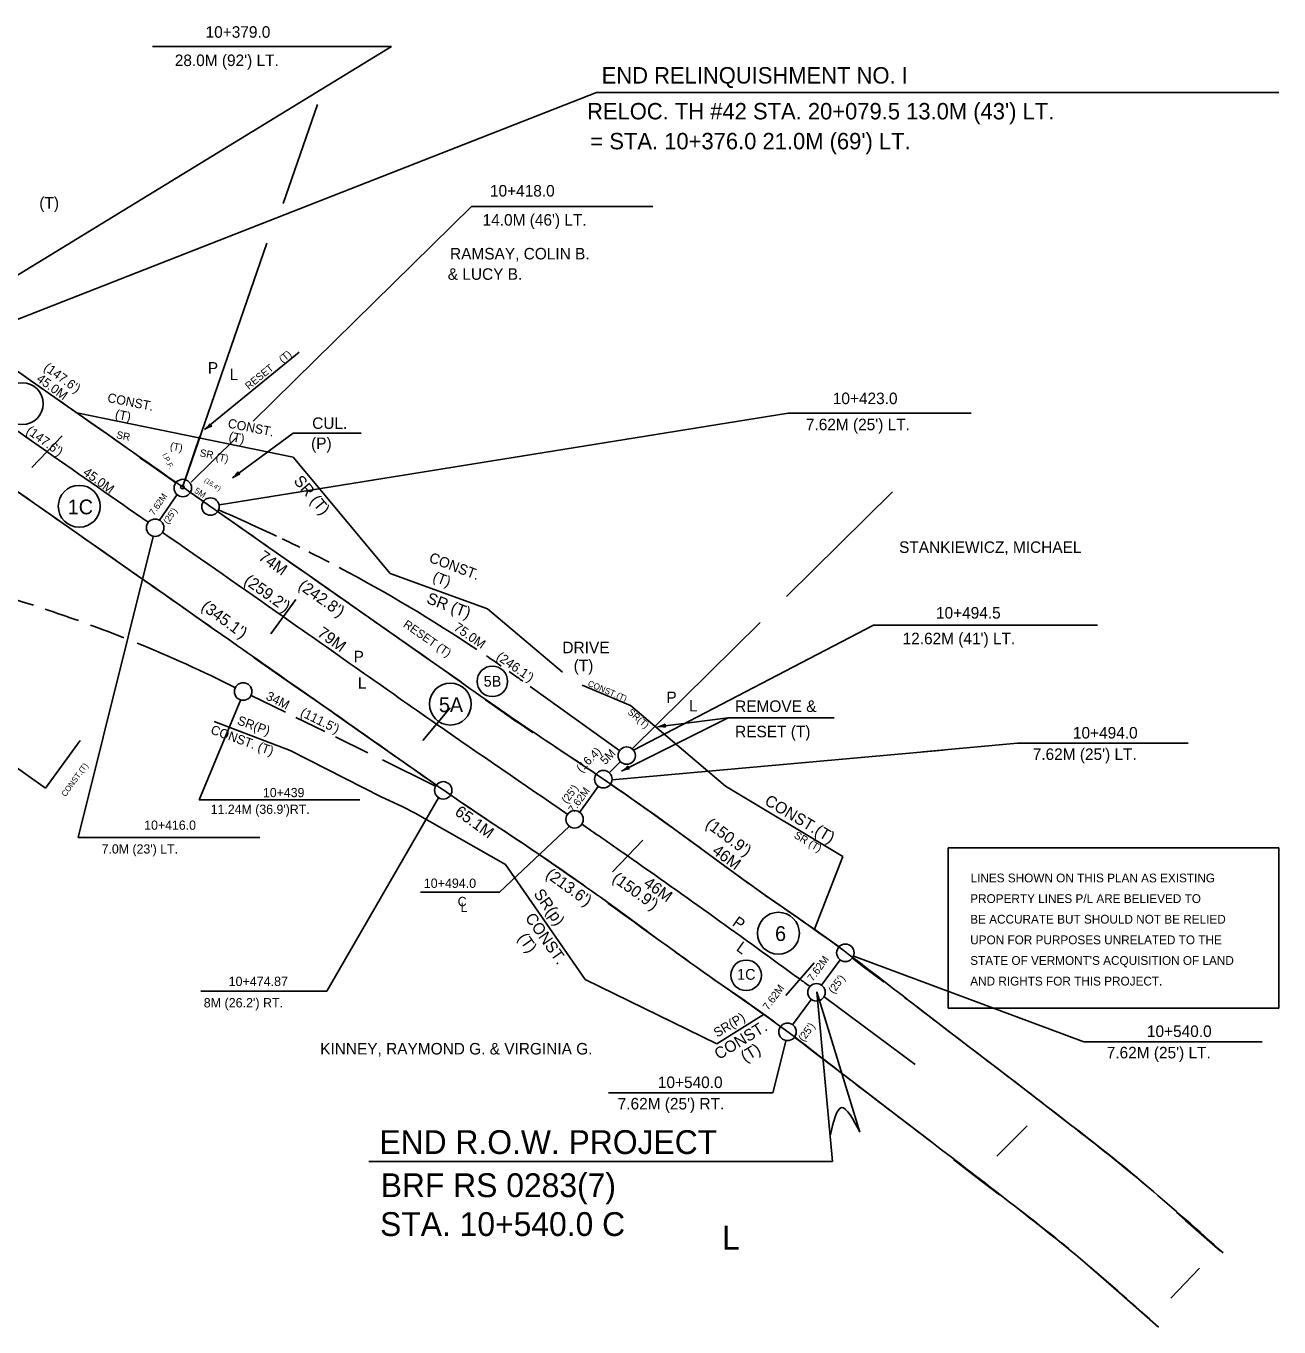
# Model space of a CAD drawing. Extents: x 624 to 1448, y 1599 to 1865.
# Drawn here: x 1254.2 to 1448.1, y 1600.9 to 1802.2 of the extents above; entities that cross this region are included whole.
import ezdxf

# ---------------------------------------------------------------- set-up
doc = ezdxf.new("R2010")
doc.units = 0
for name, color, linetype in [('C_I', 7, 'Continuous'), ('C_TIC', 7, 'Continuous'), ('CPSM', 7, 'Continuous'), ('L_A', 7, 'Continuous'), ('L_C', 7, 'Continuous'), ('L_I', 7, 'Continuous'), ('Level 16', 7, 'Continuous'), ('Level 30', 7, 'Continuous'), ('Level 60', 7, 'Continuous'), ('ODIML_P', 7, 'Continuous')]:
    doc.layers.add(name, color=color, linetype=linetype)

msp = doc.modelspace()

# ---------------------------------------------------------------- linework, layer by layer
at = {"layer": 'C_I'}
for p, q in [((1281.82, 1739.73), (1296.45, 1751.7)), ((1281.06, 1738.74), (1278.38, 1730.83)), ((1286.15, 1732.27), (1295.51, 1739.2)), ((1295.51, 1739.2), (1306.06, 1739.2)), ((1346.34, 1686.92), (1362.84, 1695.16)), ((1351.88, 1693.76), (1362.84, 1695.16)), ((1362.84, 1695.16), (1379.23, 1695.16)), ((1247.89, 1690.87), (1257.19, 1684.28)), ((1262.56, 1691.67), (1257.19, 1684.28))]:
    msp.add_line(p, q, dxfattribs=at)
msp.add_circle((1278.4, 1730.84), 0.285, dxfattribs=at)
at = {"layer": 'C_TIC'}
for p, q in [((1330.91, 1700.92), (1331.07, 1700.8)), ((1289.03, 1698.61), (1294.33, 1696.01)), ((1332.19, 1700.01), (1346.07, 1690.07)), ((1295.93, 1695.22), (1300.42, 1693.02)), ((1302.09, 1692.2), (1307.1, 1689.74)), ((1309.36, 1688.63), (1317.57, 1684.59)), ((1396.85, 1675.03), (1448.02, 1675.03)), ((1396.85, 1675.03), (1396.86, 1650.25)), ((1448.02, 1675.03), (1448.02, 1650.25)), ((1396.86, 1650.25), (1448.02, 1650.25))]:
    msp.add_line(p, q, dxfattribs=at)
for radius, start, end in [(247.62, 64.6157, 66.9012), (247.62, 63.6919, 64.3964), (247.62, 62.5203, 63.3373), (223.76, 72.1716, 79.6486), (247.62, 56.3674, 62.1142), (223.76, 70.2871, 71.6839), (223.76, 68.3594, 69.7794), (223.76, 63.542, 67.7975), (247.62, 55.3158, 55.9578), (247.62, 54.4164, 54.9691)]:
    msp.add_arc((1186.82, 1499.54), radius, start, end, dxfattribs=at)
at = {"layer": 'CPSM'}
for p, q in [((1342.48, 1791.88), (1237.06, 1750.6)), ((1342.48, 1791.88), (1448.06, 1791.88)), ((1378.99, 1626.54), (1376.57, 1652.79)), ((1376.57, 1652.79), (1383.23, 1631.07)), ((1307.26, 1626.54), (1378.99, 1626.54))]:
    msp.add_line(p, q, dxfattribs=at)
msp.add_spline([(1383.23, 1631.07), (1380.36, 1634.86), (1378.62, 1630.52)], degree=3, dxfattribs=at)
at = {"layer": 'L_C'}
for p in [(1242.65, 1757.37), (1273.78, 1798.99)]:
    msp.add_line(p, (1310.72, 1798.99), dxfattribs=at)
for centre, radius in [((1253.6, 1743.74), 3.24), ((1262.42, 1727.87), 3.24), ((1326.35, 1700.79), 2.36), ((1319.85, 1697.28), 3.24), ((1370.61, 1661.83), 3.24), ((1365.61, 1655.33), 2.36)]:
    msp.add_circle(centre, radius, dxfattribs=at)
at = {"layer": 'L_I'}
for p, q in [((1293.98, 1774.7), (1299.27, 1790.02)), ((1298.93, 1750.47), (1323.11, 1774.25)), ((1323.11, 1774.25), (1351.17, 1774.25)), ((1278.83, 1731.95), (1291.47, 1768.56)), ((1289.34, 1741.04), (1298.93, 1750.47)), ((1284.11, 1728.09), (1372.1, 1742.25)), ((1372.1, 1742.25), (1400.44, 1742.25)), ((1279.74, 1731.61), (1286.71, 1738.45)), ((1274.82, 1725.72), (1277.58, 1729.67)), ((1388.28, 1730.13), (1371.86, 1713.93)), ((1273.85, 1723.21), (1262.26, 1676.66)), ((1367.78, 1709.91), (1347.98, 1690.37)), ((1348.18, 1690.14), (1385.32, 1709.5)), ((1385.32, 1709.5), (1419.96, 1709.5)), ((1287.44, 1697.97), (1280.98, 1682.48)), ((1392.95, 1689.89), (1407.6, 1691.21)), ((1407.6, 1691.21), (1434, 1691.21)), ((1346.15, 1688.38), (1344.43, 1686.67)), ((1344.87, 1685.58), (1396.03, 1690.17)), ((1280.98, 1682.48), (1305.84, 1682.48)), ((1318.01, 1682.79), (1300.75, 1652.89)), ((1338.26, 1678.37), (1327.43, 1668.2)), ((1262.26, 1676.66), (1290.38, 1676.66)), ((1315.24, 1668.2), (1327.43, 1668.2)), ((1382.26, 1658.31), (1417.89, 1645.05)), ((1377.3, 1653.8), (1380.18, 1657.73)), ((1281.23, 1652.89), (1300.75, 1652.89)), ((1377.67, 1652.01), (1391.78, 1641.51)), ((1372.81, 1647.65), (1375.71, 1651.62)), ((1369.77, 1637.15), (1371.74, 1645.14)), ((1417.89, 1645.05), (1445.45, 1645.05)), ((1344.31, 1637.15), (1369.77, 1637.15))]:
    msp.add_line(p, q, dxfattribs=at)
msp.add_lwpolyline([(1342.73, 1684.55), (1339.85, 1680.52)], dxfattribs=at)
for centre in [(1278.45, 1730.69), (1282.73, 1727.83), (1274.17, 1724.55), (1287.79, 1699.22), (1347.14, 1689.31), (1343.52, 1685.66), (1318.75, 1683.93), (1339.07, 1679.45), (1380.97, 1658.81), (1376.5, 1652.7), (1372.02, 1646.58)]:
    msp.add_circle(centre, 1.35, dxfattribs=at)
for points in [[(1238.24, 1749.77), (1257.42, 1736.33), (1273.09, 1725.39)], [(1275.33, 1723.83), (1294, 1710.8), (1317.71, 1694.18), (1337.94, 1680.26)], [(1340.29, 1678.64), (1347.28, 1673.79), (1373.95, 1654.72), (1375.49, 1653.6)]]:
    msp.add_spline(points, degree=3, dxfattribs=at)
at = {"layer": 'Level 16'}
for p, q in [((1282.67, 1740.64), (1282.73, 1740.4)), ((1282.64, 1740.5), (1282.53, 1740.32)), ((1282.8, 1740.29), (1282.59, 1740.24)), ((1282.94, 1740.28), (1282.73, 1740.4)), ((1286.98, 1733.04), (1286.87, 1732.86)), ((1287.13, 1732.83), (1286.93, 1732.78)), ((1287.01, 1733.18), (1287.07, 1732.94)), ((1287.28, 1732.82), (1287.07, 1732.94)), ((1352.97, 1694.06), (1352.79, 1693.95)), ((1353.01, 1693.8), (1352.8, 1693.85)), ((1353.07, 1694.17), (1353.01, 1693.93)), ((1353.14, 1693.72), (1353.01, 1693.93)), ((1347.28, 1687.54), (1347.14, 1687.38)), ((1347.4, 1687.31), (1347.19, 1687.29)), ((1347.34, 1687.68), (1347.36, 1687.43)), ((1347.54, 1687.27), (1347.36, 1687.43))]:
    msp.add_line(p, q, dxfattribs=at)
for centre, start, end in [((1279.78, 1742.47), 306.5421, 327.7653), ((1283.85, 1736.98), 105.345, 126.5683), ((1284.12, 1735.01), 306.5421, 327.7653), ((1288.19, 1729.52), 105.345, 126.5683), ((1351.37, 1697.15), 278.5256, 299.7488), ((1352.39, 1690.38), 77.3285, 98.5518), ((1344.81, 1689.98), 296.5256, 317.7488), ((1347.87, 1683.86), 95.3285, 116.5518)]:
    msp.add_arc(centre, 3.42, start, end, dxfattribs=at)
at = {"layer": 'Level 30'}
for p, q in [((1347.71, 1697.05), (1340.22, 1700.19)), ((1309.13, 1682.95), (1312.39, 1681.44))]:
    msp.add_line(p, q, dxfattribs=at)
for points in [[(1295.53, 1735.49), (1262.05, 1742.32)], [(1310.56, 1717.5), (1295.53, 1735.49)], [(1325.6, 1711.99), (1310.56, 1717.5)], [(1337.18, 1702.23), (1325.6, 1711.99)], [(1362.44, 1684.59), (1347.71, 1697.05)], [(1295.05, 1690.12), (1283.3, 1694.57)], [(1309.13, 1682.95), (1295.05, 1690.12)], [(1380.56, 1673.7), (1362.44, 1684.59)], [(1328.37, 1672.47), (1314.41, 1680.41), (1312.39, 1681.44)], [(1340.69, 1654.68), (1328.37, 1672.47)], [(1376.18, 1662.45), (1380.56, 1673.7)], [(1361.1, 1644.75), (1340.69, 1654.68)], [(1368.39, 1649.3), (1361.1, 1644.75)]]:
    msp.add_lwpolyline(points, dxfattribs=at)
at = {"layer": 'Level 60'}
for p, q in [((1255.08, 1733.87), (1259.76, 1738.78)), ((1292.06, 1708.15), (1295.93, 1713.45)), ((1315.59, 1691.65), (1319.84, 1696.71)), ((1344.92, 1671.33), (1349.64, 1676.25)), ((1371.76, 1652.18), (1376.15, 1657.26)), ((1404.41, 1627.37), (1409.1, 1632.07)), ((1431.33, 1605.39), (1435.74, 1610.04))]:
    msp.add_line(p, q, dxfattribs=at)
at = {"layer": 'ODIML_P'}
for points in [[(1242.51, 1756), (1248.06, 1752.11), (1254.3, 1747.74), (1260.54, 1743.37), (1266.78, 1739), (1269.31, 1737.23)], [(1245.57, 1735.26), (1251.8, 1730.9), (1258.05, 1726.53), (1264.29, 1722.16), (1270.53, 1717.79), (1271.9, 1716.83), (1273.28, 1715.86), (1278.14, 1712.45), (1283.01, 1709.04), (1285.73, 1707.14)], [(1271.81, 1735.39), (1272.98, 1734.57), (1277.37, 1731.5)], [(1279.62, 1730.02), (1281.66, 1728.59)], [(1283.84, 1727.06), (1286.88, 1724.93), (1291.75, 1721.52), (1297.99, 1717.15), (1304.23, 1712.78), (1310.47, 1708.41), (1316.72, 1704.04), (1321.55, 1700.65)], [(1289.47, 1704.43), (1295.45, 1700.24), (1301.58, 1696.06)], [(1325.29, 1697.94), (1329.12, 1695.26), (1329.9, 1694.71), (1330.64, 1694.21), (1331.33, 1693.74), (1331.98, 1693.3), (1332.68, 1692.83)], [(1301.64, 1696), (1301.74, 1695.93), (1307.98, 1691.56), (1314.27, 1687.16), (1317.7, 1684.76)], [(1336.03, 1690.7), (1338.08, 1689.34), (1339.02, 1688.72), (1339.72, 1688.25), (1340.78, 1687.54), (1341.82, 1686.83), (1342.42, 1686.42)], [(1344.65, 1684.88), (1344.78, 1684.79), (1345.99, 1683.96), (1347.04, 1683.22), (1348.88, 1681.94), (1350.26, 1680.97), (1351.29, 1680.24), (1352.83, 1679.14), (1354.38, 1678.04), (1355.15, 1677.48), (1355.87, 1676.96), (1357.23, 1675.98), (1358.41, 1675.11), (1362.55, 1672.07), (1363.58, 1671.31), (1365.13, 1670.17), (1365.91, 1669.61), (1366.69, 1669.05), (1367.47, 1668.49), (1368.2, 1667.97), (1368.89, 1667.49), (1369.54, 1667.04), (1374.41, 1663.68), (1375.02, 1663.26), (1375.55, 1662.89), (1379.99, 1659.75)], [(1319.91, 1683.21), (1320.55, 1682.76), (1321.34, 1682.21), (1322.07, 1681.71), (1322.76, 1681.24), (1323.41, 1680.8), (1324.64, 1679.98), (1325.71, 1679.27), (1329.47, 1676.78), (1330.41, 1676.16), (1331.11, 1675.69), (1332.16, 1674.98), (1333.21, 1674.27), (1334.76, 1673.2), (1336.11, 1672.27), (1337.29, 1671.45), (1338.33, 1670.73), (1340.13, 1669.47), (1340.48, 1669.23)], [(1344.2, 1666.5), (1345.47, 1665.59), (1346.25, 1665.04), (1346.97, 1664.51), (1348.32, 1663.53), (1349.5, 1662.66), (1351.48, 1661.21)], [(1354.71, 1658.93), (1356.26, 1657.8), (1357.04, 1657.23), (1357.82, 1656.67), (1358.59, 1656.12), (1359.31, 1655.6), (1359.99, 1655.13), (1360.63, 1654.68), (1365.46, 1651.36), (1366.06, 1650.94), (1366.59, 1650.58), (1367.5, 1649.93), (1368.18, 1649.44), (1368.69, 1649.07), (1369.08, 1648.79), (1369.65, 1648.37), (1370.21, 1647.94), (1370.96, 1647.38)], [(1382.07, 1657.97), (1383.38, 1656.97), (1385.39, 1655.44), (1386.95, 1654.25)], [(1390.14, 1651.9), (1391.46, 1650.9), (1397.54, 1646.24), (1403.62, 1641.59), (1406.67, 1639.25), (1411.23, 1635.74), (1415.8, 1632.22), (1417.33, 1631.05), (1418.66, 1630.01), (1419.83, 1629.1), (1420.85, 1628.3), (1421.74, 1627.6), (1422.52, 1626.98), (1423.19, 1626.44), (1423.78, 1625.96), (1424.29, 1625.54), (1424.74, 1625.17), (1425.52, 1624.52), (1426.11, 1624.03), (1426.54, 1623.66), (1427.19, 1623.1), (1427.84, 1622.54), (1428.77, 1621.73)], [(1373.14, 1645.72), (1374.34, 1644.81), (1376.31, 1643.31), (1379.26, 1641.05), (1382.21, 1638.79), (1388.28, 1634.15), (1394.07, 1629.71)], [(1397.69, 1626.84), (1401.83, 1623.66), (1404.82, 1621.36)], [(1408, 1619), (1409.16, 1618.11), (1410.29, 1617.23), (1411.28, 1616.45), (1412.14, 1615.77), (1412.89, 1615.17), (1413.55, 1614.65), (1414.12, 1614.18), (1414.62, 1613.78), (1415.48, 1613.06), (1416.13, 1612.52), (1416.61, 1612.11), (1417.33, 1611.49), (1418.05, 1610.87), (1423.73, 1605.9), (1429.41, 1600.93)], [(1432.19, 1618.63), (1433.59, 1617.41), (1438.96, 1612.71)]]:
    msp.add_lwpolyline(points, dxfattribs=at)
for points in [[(1237.38, 1759.65), (1241.82, 1756.48), (1254.3, 1747.74), (1266.78, 1739), (1279.27, 1730.26), (1282.01, 1728.34), (1291.75, 1721.52), (1304.23, 1712.78), (1316.72, 1704.04), (1329.16, 1695.32), (1341.82, 1686.83), (1354.38, 1678.04), (1366.69, 1669.05), (1379.22, 1660.23), (1391.46, 1650.9), (1403.62, 1641.59), (1415.8, 1632.22), (1427.84, 1622.54), (1439.44, 1612.4)], [(1228.65, 1747.17), (1233, 1744.06), (1245.56, 1735.27), (1258.05, 1726.53), (1270.53, 1717.79), (1273.28, 1715.86), (1283.01, 1709.04), (1295.5, 1700.3), (1307.98, 1691.56), (1320.55, 1682.76), (1333.21, 1674.27), (1345.52, 1665.65), (1357.82, 1656.67), (1370.21, 1647.94), (1382.21, 1638.79), (1394.35, 1629.5), (1406.38, 1620.25), (1418.05, 1610.87), (1429.41, 1600.93)]]:
    msp.add_spline(points, degree=3, dxfattribs=at)

# ---------------------------------------------------------------- texts
at = {"layer": 'C_I'}
for s, p in [('(T)', (1256.25, 1773.91)), ('CUL.', (1298.47, 1739.84)), ('(P)', (1298.3, 1736.72)), ('DRIVE', (1337.19, 1705.14)), ('(T)', (1338.93, 1702.36)), ('REMOVE &', (1363.91, 1696.06)), ('RESET (T)', (1363.91, 1692.14))]:
    msp.add_text(s, height=1.783, dxfattribs=at).set_placement(p)
for s, height, rotation, p in [('(T)', 1.141, 39.2906, (1293.89, 1749.98)), ("(147.6')", 1.426, 324.0348, (1256.81, 1749.06)), ('RESET', 1.141, 39.2906, (1288.67, 1745.85)), ('45.0M', 1.426, 324.0348, (1255.69, 1747.32)), ('CONST.', 1.426, 348.7867, (1266.7, 1744.02)), ('(T)', 1.426, 348.7867, (1267.88, 1741.47)), ('CONST.', 1.426, 348.7867, (1285.33, 1740.06)), ("(147.6')", 1.426, 324.0348, (1254.09, 1739.29)), ('SR', 1.141, 348.7867, (1268.1, 1738.41)), ('(T)', 1.426, 348.7867, (1285.47, 1738.03)), ('(T)', 1.141, 348.7867, (1276.4, 1736.69)), ('SR', 1.141, 348.7867, (1281, 1735.62)), ('I.P.F.', 0.8, 296.5573, (1275.23, 1735.85)), ('(T)', 1.141, 348.7867, (1283.49, 1735.01)), ('45.0M', 1.426, 324.0348, (1262.89, 1732.84)), ('SR (T)', 1.783, 309.9901, (1295.5, 1731.75)), ('5M', 0.948, 327.817, (1280.14, 1730.04)), ("(16.4')", 0.725, 327.817, (1281.69, 1731.7)), ('7.62M', 1, 55.1081, (1273.98, 1726.39)), ("(25')", 1, 55.1081, (1276.15, 1725.03)), ('74M', 1.783, 324.9475, (1290.02, 1719.72)), ('CONST.', 1.605, 339.1794, (1316.42, 1719.3)), ("(259.2')", 1.783, 324.409, (1287.77, 1716.03)), ("(242.8')", 1.783, 324.9475, (1296.16, 1715.23)), ('(T)', 1.605, 339.1794, (1316.99, 1716.36)), ('SR (T)', 1.783, 339.1794, (1316.03, 1712.95)), ("(345.1')", 1.783, 323.9397, (1281.15, 1712.03)), ('79M', 1.783, 324.409, (1299.13, 1707.93)), ('RESET (T)', 1.3, 325.3205, (1312.44, 1709.32)), ('75.0M', 1.444, 325.2666, (1320.25, 1708.82)), ("(246.1')", 1.444, 325.2666, (1326.83, 1704.3)), ('CONST.(T)', 0.948, 337.0497, (1341.02, 1700.12)), ('34M', 1.426, 333.6516, (1291.19, 1698.05)), ("(111.5')", 1.426, 333.6516, (1296.51, 1695.52)), ('SR(T)', 1.053, 319.388, (1347.19, 1695.88)), ('SR(P)', 1.426, 340.1043, (1286.76, 1694.18)), ('CONST. (T)', 1.426, 340.1043, (1282.64, 1692.75)), ('(16.4)', 1.3, 44.9803, (1340.1, 1686.62)), ('5M', 1.3, 44.9803, (1343.82, 1687.82)), ('CONST.(T)', 0.891, 54.0302, (1260.31, 1682.88)), ("(25')", 1.17, 53.8192, (1337.9, 1681.79)), ('7.62M', 1.17, 53.8192, (1338.93, 1680.35)), ('CONST.(T)', 1.783, 329.0918, (1368.32, 1681.85)), ('65.1M', 1.783, 324.1613, (1320.4, 1680.27)), ("(150.9')", 1.783, 323.6344, (1359.17, 1678.38)), ('SR (T)', 1.17, 329.0918, (1372.91, 1676.68)), ('46M', 1.783, 323.6344, (1360.23, 1674.26)), ("(213.6')", 1.783, 324.1613, (1334.45, 1670.6)), ("(150.9')", 1.783, 324.2792, (1344.75, 1669.98)), ('46M', 1.783, 324.2792, (1349.62, 1669.24)), ('SR(p)', 1.783, 304.9564, (1332.65, 1667.93)), ('CONST.', 1.783, 304.9564, (1331.33, 1664.21)), ('(T)', 1.783, 304.9564, (1330.2, 1661.12)), ('7.62M', 1.17, 53.8192, (1375.93, 1654.29)), ("(25')", 1.17, 53.8192, (1379.17, 1652.39)), ('7.62M', 1.17, 53.8192, (1369.02, 1649.84)), ('SR(P)', 1.444, 31.3933, (1361.14, 1645.67)), ('CONST.', 1.783, 31.3933, (1361.39, 1642.21)), ("(25')", 1.17, 53.8192, (1374.52, 1644.98)), ('(T)', 1.783, 31.3933, (1365.45, 1641.82))]:
    msp.add_text(s, height=height, rotation=rotation, dxfattribs=at).set_placement(p)
at = {"layer": 'C_TIC'}
for s, p in [('LINES SHOWN ON THIS PLAN AS EXISTING', (1400.34, 1669.7)), ('BE ACCURATE BUT SHOULD NOT BE RELIED', (1400.29, 1663.32)), ('UPON FOR PURPOSES UNRELATED TO THE', (1400.29, 1660.13)), ("STATE OF VERMONT'S ACQUISITION OF LAND", (1400.29, 1656.94)), ('AND RIGHTS FOR THIS PROJECT.', (1400.29, 1653.75))]:
    msp.add_text(s, height=1.3608, dxfattribs=at).set_placement(p)
msp.add_text('PROPERTY LINES P/L ARE BELIEVED TO', height=1.3608, rotation=0.0007, dxfattribs=at).set_placement((1400.29, 1666.51))
at = {"layer": 'CPSM'}
for s, height, p in [('END RELINQUISHMENT NO. I', 2.54, (1343.26, 1793.26)), ("RELOC. TH #42 STA. 20+079.5 13.0M (43') LT.", 2.54, (1341, 1787.71)), ("= STA. 10+376.0 21.0M (69') LT.", 2.54, (1341.52, 1783.08)), ('END R.O.W. PROJECT', 3.683, (1308.87, 1627.69)), ('BRF RS 0283(7)', 3.683, (1309.07, 1621.02)), ('STA. 10+540.0 C', 3.683, (1308.97, 1615.01)), ('L', 3.68, (1361.91, 1612.9))]:
    msp.add_text(s, height=height, dxfattribs=at).set_placement(p)
at = {"layer": 'L_A'}
for s, p in [('RAMSAY, COLIN B. ', (1319.8, 1766.05)), ('& LUCY B.', (1319.45, 1762.9)), ('STANKIEWICZ, MICHAEL', (1389.28, 1720.66)), ('KINNEY, RAYMOND G. & VIRGINIA G.', (1299.71, 1643.08))]:
    msp.add_text(s, height=1.783, dxfattribs=at).set_placement(p)
at = {"layer": 'L_C'}
for s, height, p in [('10+379.0', 1.783, (1281.98, 1800.34)), ("28.0M (92') LT.", 1.783, (1277.21, 1795.96)), ('10+418.0', 1.783, (1325.98, 1775.78)), ("14.0M (46') LT.", 1.783, (1324.84, 1771.28)), ('10+423.0', 1.783, (1379.03, 1743.67)), ("7.62M (25') LT.", 1.783, (1374.86, 1739.64)), ('1C', 2.286, (1260.65, 1726.63)), ('10+494.5', 1.783, (1394.99, 1710.5)), ("12.62M (41') LT.", 1.783, (1389.83, 1706.53)), ('5B', 1.666, (1325, 1699.98)), ('5A', 2.286, (1318.08, 1696.03)), ('10+494.0', 1.783, (1416.18, 1691.95)), ("7.62M (25') LT.", 1.783, (1409.96, 1688.64)), ('10+439', 1.426, (1290.85, 1682.88)), ("11.24M (36.9')RT.", 1.426, (1282.77, 1680.3)), ('10+416.0', 1.426, (1272.48, 1677.84)), ("7.0M (23') LT.", 1.4264, (1265.89, 1674.16)), ('10+494.0', 1.444, (1315.73, 1668.85)), ('C', 1.44, (1320.98, 1666.02)), ('L', 1.44, (1321.43, 1665.12)), ('6', 2.29, (1370.09, 1660.64)), ('1C', 1.666, (1364.22, 1654.64)), ('10+474.87', 1.444, (1285.54, 1653.67)), ("8M (26.2') RT.", 1.444, (1281.69, 1650.36)), ('10+540.0', 1.783, (1427.63, 1645.79)), ("7.62M (25') LT.", 1.783, (1421.41, 1642.48)), ('10+540.0', 1.783, (1351.96, 1637.89)), ("7.62M (25') RT.", 1.783, (1345.74, 1634.58))]:
    msp.add_text(s, height=height, dxfattribs=at).set_placement(p)
at = {"layer": 'L_I'}
for s, p in [('P', (1282.33, 1748.39)), ('L', (1285.7, 1747.38)), ('P', (1304.88, 1703.74)), ('L', (1305.53, 1699.66)), ('P', (1353.28, 1697.43)), ('L', (1356.78, 1696.14))]:
    msp.add_text(s, height=1.78, dxfattribs=at).set_placement(p)
for s, p in [('P', (1363.34, 1663.14)), ('L', (1363.95, 1659.25))]:
    msp.add_text(s, height=1.78, rotation=324.6975, dxfattribs=at).set_placement(p)

doc.saveas('drawing.dxf')
